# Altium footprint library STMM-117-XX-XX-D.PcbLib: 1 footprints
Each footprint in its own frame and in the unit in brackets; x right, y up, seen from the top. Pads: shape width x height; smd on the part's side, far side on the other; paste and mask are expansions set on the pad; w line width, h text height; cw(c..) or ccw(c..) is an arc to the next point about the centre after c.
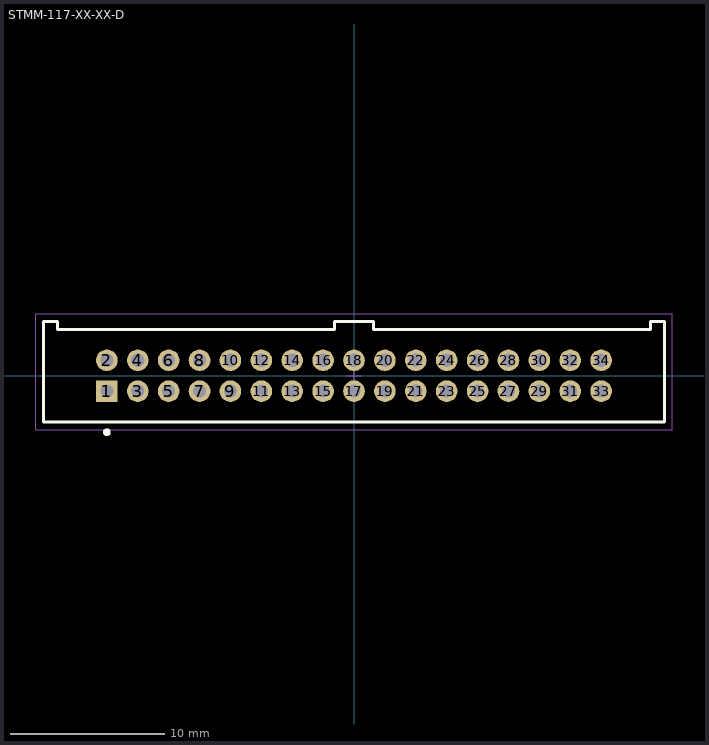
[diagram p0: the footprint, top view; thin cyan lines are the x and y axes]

## STMM-117-XX-XX-D [mm] "2.00mm pitch, 34 pin, terminal strip; shrouded, double row, PTH"
height 4.8
pads (34):
  rect 1.4x1.4 / inner round 1.4 / far side rect 1.4x1.4 hole 0.85 mask+0: 1(-16,-1)
  round 1.4 hole 0.85 mask+0: 2(-16,1) 3(-14,-1) 4(-14,1) 5(-12,-1) 6(-12,1) 7(-10,-1) 8(-10,1) 9(-8,-1) 10(-8,1) 11(-6,-1) 12(-6,1) 13(-4,-1) 14(-4,1) 15(-2,-1) 16(-2,1) 17(0,-1) 18(0,1) 19(2,-1) 20(2,1) 21(4,-1) 22(4,1) 23(6,-1) 24(6,1) 25(8,-1) 26(8,1) 27(10,-1) 28(10,1) 29(12,-1) 30(12,1) 31(14,-1) 32(14,1) 33(16,-1) 34(16,1)
Top Overlay:
  circle w0.25: c-16,-3.65 r0.125
  lines w0.2: -20.1,-3 20.1,-3 20.1,3.5 19.2,3.5 19.2,3 1.25,3 1.25,3.5 -1.25,3.5 -1.25,3 -19.2,3 -19.2,3.5 -20.1,3.5 -20.1,-3
Mechanical 12:
  lines w0.001: -20.1,-3 20.1,-3 20.1,3.5 19.2,3.5 19.2,3 1.25,3 1.25,3.5 -1.25,3.5 -1.25,3 -19.2,3 -19.2,3.5 -20.1,3.5 -20.1,-3
Mechanical 13:
  lines w0.1: -20.1,-3 20.1,-3 20.1,3.5 19.2,3.5 19.2,3 1.25,3 1.25,3.5 -1.25,3.5 -1.25,3 -19.2,3 -19.2,3.5 -20.1,3.5 -20.1,-3
  text ".Designator" at 0,-0.127 h1.52
Mechanical 15:
  lines w0.05: -0.5,0 0.5,0 ; 0,-0.5 0,0.5 ; -20.6,-3.5 20.6,-3.5 20.6,4 -20.6,4 -20.6,-3.5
